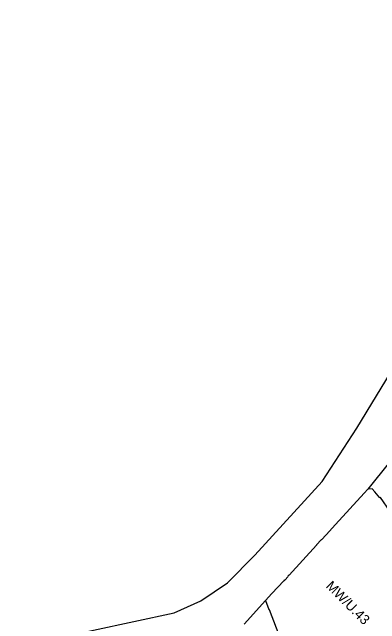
# Model space of a CAD drawing. Extents: x 7423835 to 7425280, y 5546086 to 5547600.
# Drawn here: x 7424002.9 to 7424227.3, y 5546605 to 5546978.5 of the extents above; entities that cross this region are included whole.
import ezdxf

# ---------------------------------------------------------------- set-up
doc = ezdxf.new("R2010")
doc.units = 0
for name, color, linetype in [('linie rozgraniczające', 7, 'Continuous'), ('obowiazujace linie zabudowy', 7, 'Continuous'), ('przeznaczenia terenów', 7, 'Continuous')]:
    doc.layers.add(name, color=color, linetype=linetype)

msp = doc.modelspace()

# ---------------------------------------------------------------- linework, layer by layer
at = {"layer": 'linie rozgraniczające'}
for p, q in [((7424192.12, 5546691.87), (7424213.38, 5546724.52)), ((7424233.24, 5546703.71), (7424220.01, 5546687.22)), ((7424151.04, 5546646.88), (7424192.12, 5546691.87)), ((7424101.85, 5546611.78), (7424118.19, 5546619)), ((7424144.53, 5546604.8), (7424157.55, 5546619.31)), ((7424002.95, 5546590.54), (7424101.85, 5546611.78))]:
    msp.add_line(p, q, dxfattribs=at)
for points in [[(7424213.38, 5546724.52), (7424267.06, 5546812.79), (7424421.63, 5547117.9)], [(7424220.01, 5546687.22), (7424217.72, 5546684.69), (7424200.27, 5546665.7), (7424200.23, 5546665.59), (7424194.62, 5546659.41), (7424191.7, 5546656.2), (7424191.56, 5546656.28), (7424188.69, 5546653.27), (7424188.8, 5546653.11), (7424180.46, 5546643.95), (7424172.01, 5546634.7), (7424171.9, 5546634.78), (7424171.17, 5546634.02), (7424171.37, 5546633.85), (7424169.41, 5546631.73), (7424169.24, 5546631.9), (7424168.69, 5546631.34), (7424168.82, 5546631.22), (7424161.52, 5546623.42), (7424161.42, 5546623.55), (7424157.55, 5546619.31)], [(7424253.09, 5546597.9), (7424248.43, 5546615.1), (7424248.72, 5546615.23), (7424252.65, 5546616), (7424251.4, 5546620.2), (7424246.8, 5546634.55), (7424241.34, 5546651.77), (7424240.95, 5546653.11), (7424238.34, 5546660.94), (7424238.09, 5546661.56), (7424233.76, 5546673.51), (7424227.76, 5546682.21), (7424227.37, 5546681.92), (7424224.28, 5546685.65), (7424222.66, 5546687.33), (7424220.01, 5546687.22)], [(7424118.19, 5546619), (7424134.38, 5546630.1), (7424151.04, 5546646.88)], [(7424157.55, 5546619.31), (7424159.67, 5546613.74), (7424159.81, 5546613.79), (7424168.34, 5546591.3), (7424168.02, 5546591.18), (7424168.78, 5546588.78), (7424168.69, 5546588.75), (7424172.21, 5546578.7), (7424172.36, 5546578.77), (7424173.58, 5546575.25), (7424173.51, 5546575.17), (7424175.76, 5546568.72), (7424175.62, 5546568.67), (7424177, 5546564.76), (7424177.16, 5546564.8), (7424178.96, 5546559.74)]]:
    msp.add_lwpolyline(points, dxfattribs=at)
at = {"layer": 'obowiazujace linie zabudowy'}
for points in [[(7424220.01, 5546687.22), (7424217.72, 5546684.69), (7424200.27, 5546665.7), (7424200.23, 5546665.59), (7424194.62, 5546659.41), (7424191.7, 5546656.2), (7424191.56, 5546656.28), (7424188.69, 5546653.27), (7424188.8, 5546653.11), (7424180.46, 5546643.95), (7424172.01, 5546634.7), (7424171.9, 5546634.78), (7424171.17, 5546634.02), (7424171.37, 5546633.85), (7424169.41, 5546631.73), (7424169.24, 5546631.9), (7424168.69, 5546631.34), (7424168.82, 5546631.22), (7424161.52, 5546623.42), (7424161.42, 5546623.55), (7424157.55, 5546619.31)], [(7424253.09, 5546597.9), (7424248.43, 5546615.1), (7424248.72, 5546615.23), (7424252.65, 5546616), (7424251.4, 5546620.2), (7424246.8, 5546634.55), (7424241.34, 5546651.77), (7424240.95, 5546653.11), (7424238.34, 5546660.94), (7424238.09, 5546661.56), (7424233.76, 5546673.51), (7424227.76, 5546682.21), (7424227.37, 5546681.92), (7424224.28, 5546685.65), (7424222.66, 5546687.33), (7424220.01, 5546687.22)], [(7424157.55, 5546619.31), (7424159.67, 5546613.74), (7424159.81, 5546613.79), (7424168.34, 5546591.3), (7424168.02, 5546591.18), (7424168.78, 5546588.78), (7424168.69, 5546588.75), (7424172.21, 5546578.7), (7424172.36, 5546578.77), (7424173.58, 5546575.25), (7424173.51, 5546575.17), (7424175.76, 5546568.72), (7424175.62, 5546568.67), (7424177, 5546564.76), (7424177.16, 5546564.8), (7424178.96, 5546559.74)]]:
    msp.add_lwpolyline(points, dxfattribs=at)

# ---------------------------------------------------------------- texts
at = {"layer": 'przeznaczenia terenów'}
msp.add_text('MW/U.43', height=6, rotation=314.9764, dxfattribs=at).set_placement((7424194.01, 5546627.58))

doc.saveas('drawing.dxf')
